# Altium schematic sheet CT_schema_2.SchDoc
size 300 x 163 mm
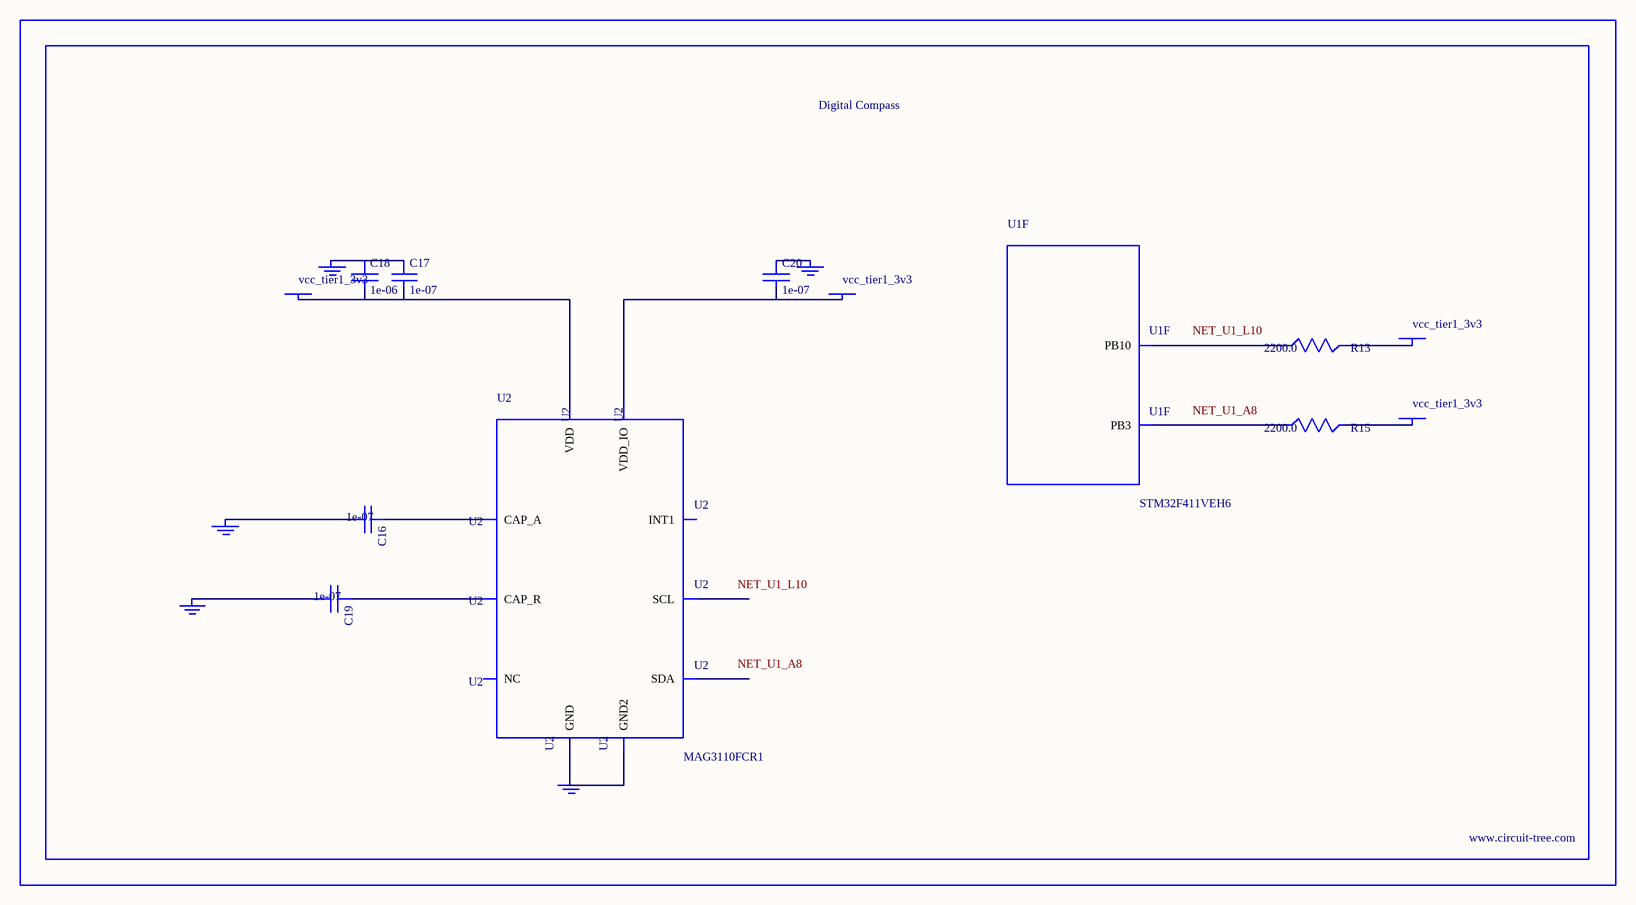
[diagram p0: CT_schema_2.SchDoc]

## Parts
BORDER1  (no value)
C16  1e-07  [C0402]
C17  1e-07  [C0402]
C18  1e-06  [C0603]
C19  1e-07  [C0402]
C20  1e-07  [C0402]
GND_INSTANCE_1_0  (no value)
GND_INSTANCE_1_1  (no value)
GND_INSTANCE_1_2  (no value)
GND_INSTANCE_1_3  (no value)
GND_INSTANCE_1_4  (no value)
POWER_INSTANCE_1_0  vcc_tier1_3v3
POWER_INSTANCE_1_1  vcc_tier1_3v3
POWER_INSTANCE_1_2  vcc_tier1_3v3
POWER_INSTANCE_1_3  vcc_tier1_3v3
R13  2200.0  [R0603]
R15  2200.0  [R0603]
U1  STM32F411VEH6  [UFBGA100]  (part F of 8)
U2  MAG3110FCR1  [DFN-10]

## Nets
NetC16_1: C16.1 U2.1(CAP_A)
NetC16_2: C16.2 GND_INSTANCE_1_0.0(GND)
NetC17_1: C17.1 C18.1 GND_INSTANCE_1_1.0(GND)
NetC17_2: C17.2 C18.2 POWER_INSTANCE_1_0.0(PWR) U2.2(VDD)
NetC19_1: C19.1 U2.4(CAP_R)
NetC19_2: C19.2 GND_INSTANCE_1_2.0(GND)
NetC20_1: C20.1 GND_INSTANCE_1_3.0(GND)
NetC20_2: C20.2 POWER_INSTANCE_1_1.0(PWR) U2.8(VDD_IO)
NetGND_INSTANCE_1_4_0: GND_INSTANCE_1_4.0(GND) U2.5(GND) U2.10(GND2)
NetPOWER_INSTANCE_1_2_0: POWER_INSTANCE_1_2.0(PWR) R13.2
NetPOWER_INSTANCE_1_3_0: POWER_INSTANCE_1_3.0(PWR) R15.2
NetR13_1: R13.1 U1.L10(PB10)
NetR15_1: R15.1 U1.A8(PB3)

Not connected (* = marked no-connect by the designer): U2 3(NC) 6(SDA) 7(SCL) 9(INT1)

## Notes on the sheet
- Labels drawn without touching a wire or pin: NET_U1_A8, NET_U1_L10

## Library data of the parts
BORDER1 = BORDER_PAGE1
C16 C17 C19 C20 = C0402C104K3RACTU
C18 = C0603C105K3RACTU
GND_INSTANCE_1_0-GND_INSTANCE_1_4 = GND
POWER_INSTANCE_1_0-POWER_INSTANCE_1_3 = PWR
R13 R15 = RC0603JR-072K2L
